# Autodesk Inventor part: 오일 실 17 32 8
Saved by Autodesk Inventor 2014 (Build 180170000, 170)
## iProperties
Created: 2026-07
Part Number: 오일 실 17 32 8
Material: 고무
Document SubType Name: Modeling
Designer: dg
Density: 0.93 g/cm^3
Appearance: 고무 - 검은색 - 버전 1.1
Mass: 1.89534 g
Surface Area: 30.829 cm^2
Volume: 2.038 cm^3
Author: jhkim
Description: 오일-실
Creation Date: 2026-07-02
Sending System: Autodesk Inventor 2027
Preprocessor: ST-DEVELOPER v20.1
Author: dg
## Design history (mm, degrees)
node "오일 실 17 32 81"
body "Solid1"
node "기준1"
